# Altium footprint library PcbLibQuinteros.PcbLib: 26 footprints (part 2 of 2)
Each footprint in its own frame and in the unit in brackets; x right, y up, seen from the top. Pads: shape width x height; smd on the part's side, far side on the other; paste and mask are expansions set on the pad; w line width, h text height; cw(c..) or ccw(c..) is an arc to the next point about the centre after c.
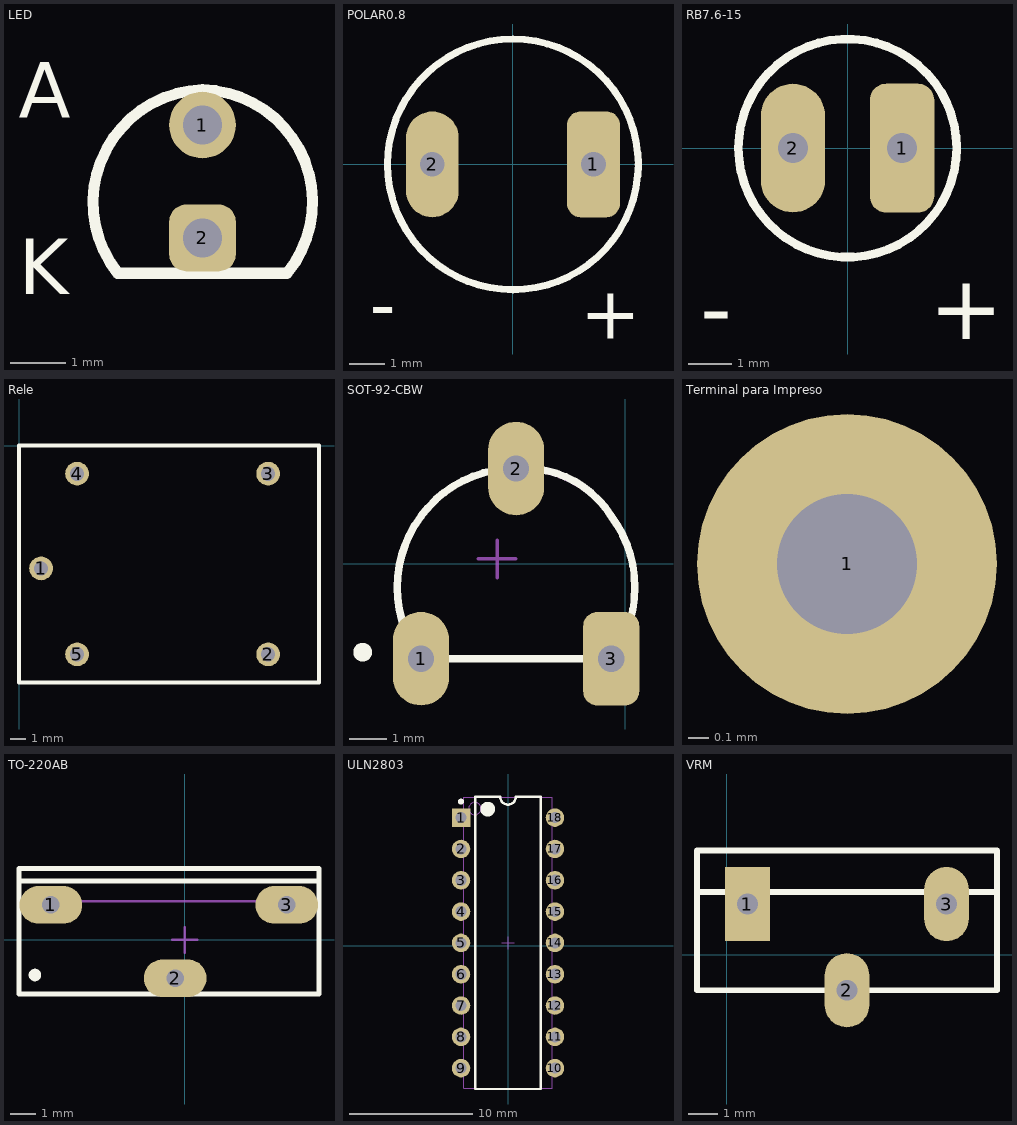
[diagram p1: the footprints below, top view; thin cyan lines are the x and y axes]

## LED [mm] "LED; 2 Leads"
pads (2):
  round 1.2 hole 0.7: 1(6.1,5.937)
  rrect50% 1.2x1.2 hole 0.7: 2(6.1,3.905)
Top Overlay:
  lines w0.2: 4.576,3.27 cw(c6.164,4.54) 6.1,6.572 cw(c6.056,4.549) 7.624,3.27 4.576,3.27
  text "A" at 2.798,6.064 h1
  text "K" at 2.798,2.889 h1

## PCBComponent_1 [mm]

## POLAR0.8 [mm] "Polarized Capacitor; 2 Leads"
height 5.08
pads (2):
  rrect50% 1.5x3 hole 0.7: 1(2.286,0)
  oval 1.5x3 hole 0.7: 2(-2.286,0)
Top Overlay:
  circle w0.2: c0,0 r3.556
  text "-" at -4.064,-4.699 h1.5
  text "+" at 1.905,-4.953 h1.5

## RB7.6-15 [mm] "Polarized Capacitor (Radial); 2 Leads"
pads (2):
  rrect50% 1.5x3 hole 0.7: 1(1.27,0)
  oval 1.5x3 hole 0.7: 2(-1.27,0)
Top Overlay:
  circle w0.2: c0,0 r2.54
  text "-" at -3.429,-4.445 h1.5
  text "+" at 1.905,-4.445 h1.5

## Rele [mm]
pads (5):
  round 1.5 hole 0.9: 1(1.397,-7.78) 2(15.777,-13.22) 3(15.777,-1.78) 4(3.677,-1.78) 5(3.677,-13.22)
Top Overlay:
  lines w0.254: 0,-15 0,0 19,0 19,-15 0,-15

## SOT-92-CBW [mm] "TO, Flat Index; 3 In-Line, Axial Leads; Body Dia. 4.5mm; Leads 0.51 x 0.48 mm (max)"
height 6.86
pads (3):
  oval 1.5x2.5 hole 0.7: 1(-5.461,-2.54) 2(-2.921,2.54)
  rrect50% 1.5x2.5 hole 0.7: 3(-0.381,-2.54)
Top Overlay:
  circle w0.25: c-7.021,-2.366 r0.125
  lines w0.2: -5.461,-2.54 cw(c-2.921,-0.635) -5.461,1.27 cw(c-2.953,-0.572) -2.921,2.54 cw(c-2.694,-0.181) -0.381,1.27 cw(c-2.921,-0.635) -0.381,-2.54 -5.461,-2.54
Mechanical 13:
  lines w0.1: -5.461,-2.54 cw(c-2.921,-0.635) -5.461,1.27 cw(c-2.953,-0.572) -2.921,2.54 cw(c-2.889,-0.572) -0.381,1.27 cw(c-2.921,-0.635) -0.381,-2.54 -5.461,-2.54
Mechanical 15:
  lines w0.1: -3.929,0.127 -2.929,0.127 ; -3.429,-0.373 -3.429,0.627
3D body: height 6.86, standoff 2.2, extent -6.111,-2.54 0.269,2.571

## Terminal para Impreso [mm]
pads (1):
  round 1.5 hole 0.7: 1(-131,68.5)

## TO-220AB [mm] "TO, Thru-Hole, Vertical, Heatsink Mounted; 3 In-Line Leads; Pitch 2.54 mm"
height 19.3
pads (3):
  oval 2.5x1.5 hole 0.7: 1(-5.334,1.397) 2(-0.381,-1.524) 3(4.064,1.397)
Top Overlay:
  circle w0.25: c-5.969,-1.397 r0.125
  lines w0.2: -6.604,2.35 5.35,2.35 ; -6.604,-2.159 -6.604,2.85 5.35,2.85 5.35,-2.159 -6.604,-2.159
Mechanical 13:
  lines w0.1: -6.604,1.55 5.35,1.55 ; -6.604,-2.159 5.35,-2.159 5.35,2.85 -6.604,2.85 -6.604,-2.159
Mechanical 15:
  lines w0.1: -0.5,0 0.5,0 ; 0,-0.5 0,0.5
3D body: height 12.9, standoff 4, extent -6.604,-2.159 5.4,2.9
3D body: height 19.3, standoff 12.9, extent -5.349,1.551 5.349,2.849

## ULN2803 [mm]
pads (18):
  rect 1.5x1.5 hole 0.9: 1(-3.841,10.374)
  round 1.5 hole 0.9: 2(-3.841,7.834) 3(-3.841,5.294) 4(-3.841,2.754) 5(-3.841,0.214) 6(-3.841,-2.326) 7(-3.841,-4.866) 8(-3.841,-7.406) 9(-3.841,-9.946) 10(3.779,-9.946) 11(3.779,-7.406) 12(3.779,-4.866) 13(3.779,-2.326) 14(3.779,0.214) 15(3.779,2.754) 16(3.779,5.294) 17(3.779,7.834) 18(3.779,10.374)
Top Overlay:
  circle w0.6: c-1.681,11.064 r0.3
  circle w0.25: c-3.841,11.674 r0.125
  lines w0.2: -2.681,-11.636 2.619,-11.636 2.619,12.064 0.604,12.064 cw(c-0.031,12.064) -0.666,12.064 -2.681,12.064 -2.681,-11.636
Mechanical 13:
  circle w0.1: c-2.731,11.114 r0.5
  lines w0.1: -3.631,-11.586 3.569,-11.586 3.569,12.014 -3.631,12.014 -3.631,-11.586
Mechanical 15:
  lines w0.1: -0.531,0.214 0.469,0.214 ; -0.031,-0.286 -0.031,0.714
3D body: height 5.08, standoff 0, extent -3.631,-11.586 3.569,12.014

## VRM [mm] "Connector; Header; 3 Position"
pads (3):
  rect 1.5x2.5 hole 0.7: 1(0.7,1.7)
  oval 1.5x2.5 hole 0.7: 2(4.05,-1.2) 3(7.4,1.7)
Top Overlay:
  lines w0.2: -1,2.1 -1,-1.2 9.1,-1.2 9.1,2.1 ; -1,2.1 9.1,2.1 ; -1,2.1 -1,3.5 9.1,3.5 9.1,2.1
